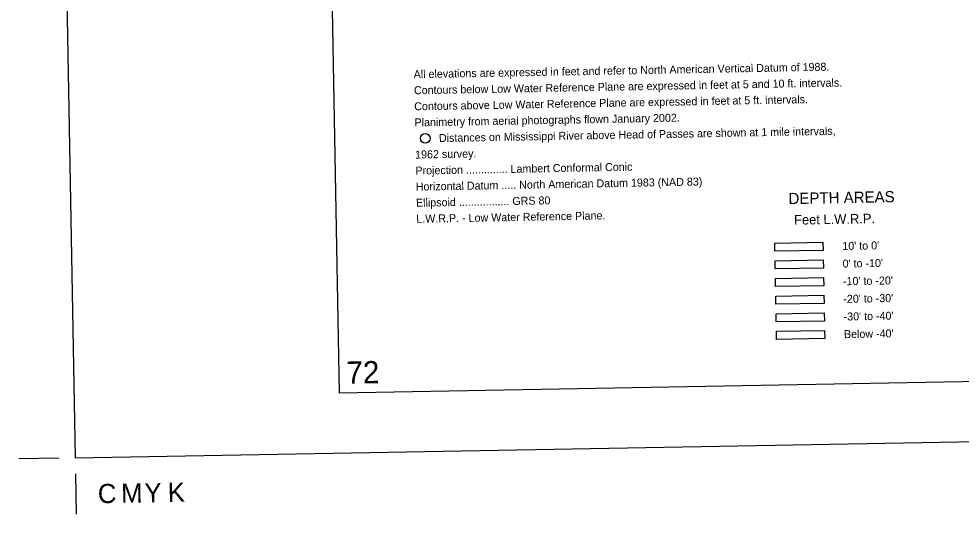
# Model space of a CAD drawing. Extents: x 3925854 to 3964121, y 224593 to 250589.
# Drawn here: x 3926294 to 3936067, y 224593 to 229731 of the extents above; entities that cross this region are included whole.
import ezdxf

# ---------------------------------------------------------------- set-up
doc = ezdxf.new("R2010")
doc.units = 0
for name, color, linetype in [('G-ANNO-NPLT', 7, 'Continuous'), ('V-ANNO-DIMS', 7, 'Continuous'), ('V-ANNO-NOTE', 7, 'Continuous'), ('V-ANNO-SYMB', 7, 'Continuous'), ('V-ANNO-TEXT', 7, 'Continuous'), ('V-TOPO-DPTH', 7, 'Continuous')]:
    doc.layers.add(name, color=color, linetype=linetype)

msp = doc.modelspace()

# ---------------------------------------------------------------- linework, layer by layer
at = {"layer": 'G-ANNO-NPLT'}
msp.add_lwpolyline([(3926876.838, 225176.36), (3963537.445, 225842.962), (3963098.093, 250005.635), (3926437.486, 249339.033)], close=True, dxfattribs=at)
at = {"layer": 'V-ANNO-DIMS'}
for p, q in [((3926710.199, 225173.33), (3926293.601, 225165.755)), ((3926879.868, 225009.721), (3926887.443, 224593.122))]:
    msp.add_line(p, q, dxfattribs=at)
at = {"layer": 'V-ANNO-NOTE'}
msp.add_circle((3930508.872, 228492.063), 50, dxfattribs=at)
at = {"layer": 'V-ANNO-SYMB'}
msp.add_lwpolyline([(3929615.153, 225851.3), (3962692.886, 226452.755), (3962276.261, 249365.543), (3929198.528, 248764.088), (3929615.153, 225851.3)], dxfattribs=at)
at = {"layer": 'V-TOPO-DPTH'}
for points in [[(3934134.05, 227404.6), (3934633.968, 227413.69), (3934635.513, 227328.704), (3934135.595, 227319.614)], [(3934134.05, 227404.6), (3934633.968, 227413.69), (3934635.513, 227328.704), (3934135.595, 227319.614)], [(3934137.377, 227221.63), (3934637.295, 227230.72), (3934638.84, 227145.734), (3934138.922, 227136.644)], [(3934137.377, 227221.63), (3934637.295, 227230.72), (3934638.84, 227145.734), (3934138.922, 227136.644)], [(3934140.704, 227038.661), (3934640.621, 227047.751), (3934642.167, 226962.765), (3934142.249, 226953.675)], [(3934140.704, 227038.661), (3934640.621, 227047.751), (3934642.167, 226962.765), (3934142.249, 226953.675)], [(3934144.031, 226855.691), (3934643.948, 226864.781), (3934645.494, 226779.795), (3934145.576, 226770.705)], [(3934144.031, 226855.691), (3934643.948, 226864.781), (3934645.494, 226779.795), (3934145.576, 226770.705)], [(3934147.358, 226672.721), (3934647.275, 226681.811), (3934648.821, 226596.825), (3934148.903, 226587.735)], [(3934147.358, 226672.721), (3934647.275, 226681.811), (3934648.821, 226596.825), (3934148.903, 226587.735)], [(3934150.685, 226489.751), (3934650.602, 226498.841), (3934652.148, 226413.855), (3934152.23, 226404.765)], [(3934150.685, 226489.751), (3934650.602, 226498.841), (3934652.148, 226413.855), (3934152.23, 226404.765)]]:
    msp.add_lwpolyline(points, close=True, dxfattribs=at)

# ---------------------------------------------------------------- texts
at = {"layer": 'V-ANNO-DIMS'}
for s, p in [('C', (3927114.387, 224705.967)), ('M', (3927356.017, 224710.361)), ('Y', (3927597.648, 224714.754)), ('K', (3927839.279, 224719.148))]:
    msp.add_text(s, height=199.267, rotation=1.041699, dxfattribs=at).set_placement(p)
at = {"layer": 'V-ANNO-NOTE'}
for s, rotation, p in [('All elevations are expressed in feet and refer to North American Vertical Datum of 1988.', 1.0417069, (3930389.271, 229115.292)), ('Contours below Low Water Reference Plane are expressed in feet at 5 and 10 ft. intervals.', 1.0417069, (3930392.302, 228948.619)), ('Contours above Low Water Reference Plane are expressed in feet at 5 ft. intervals.', 1.0417069, (3930395.333, 228781.947)), ('Planimetry from aerial photographs flown January 2002.', 1.0417069, (3930398.362, 228615.274)), ('Distances on Mississippi River above Head of Passes are shown at 1 mile intervals,', 1.0417069, (3930651.55, 228453.15)), ('1962 survey.', 1.0417069, (3930404.424, 228281.929)), ('Projection .............. Lambert Conformal Conic', 1.0416764, (3930407.454, 228115.276)), ('Horizontal Datum ..... North American Datum 1983 (NAD 83)', 1.0416764, (3930410.485, 227948.603)), ('Ellipsoid ................. GRS 80', 1.0416764, (3930413.516, 227781.93)), ('L.W.R.P. - Low Water Reference Plane.', 1.0416764, (3930416.547, 227615.258))]:
    msp.add_text(s, height=83, rotation=rotation, dxfattribs=at).set_placement(p)
at = {"layer": 'V-ANNO-TEXT'}
msp.add_text('72', height=230, rotation=1.0417, dxfattribs=at).set_placement((3929692.932, 225946.06))
at = {"layer": 'V-TOPO-DPTH'}
for s, height, rotation, p in [('DEPTH AREAS', 116.7, 1.0417124, (3934277.406, 227808.942)), ('Feet L.W.R.P.', 100, 1.0417007, (3934335.001, 227595.789)), ("10' to 0'", 83, 1.0417007, (3934835.462, 227333.34)), ("0' to -10'", 83, 1.0417007, (3934838.789, 227150.37)), ("-10' to -20'", 83, 1.0417007, (3934842.116, 226967.401)), ("-20' to -30'", 83, 1.0417007, (3934845.443, 226784.431)), ("-30' to -40'", 83, 1.0417007, (3934848.769, 226601.461)), ("Below -40'", 83, 1.0417007, (3934852.096, 226418.491))]:
    msp.add_text(s, height=height, rotation=rotation, dxfattribs=at).set_placement(p)

doc.saveas('drawing.dxf')
